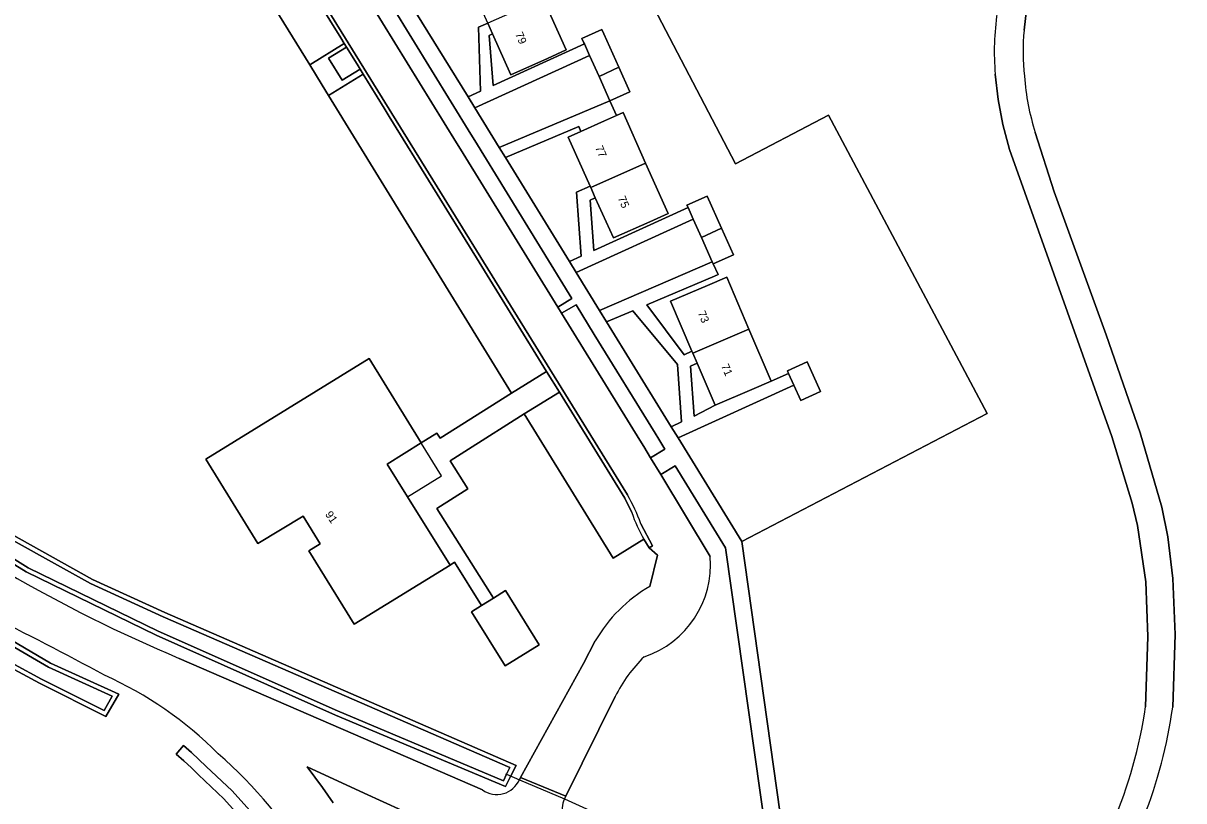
# Model space of a CAD drawing. Extents: x 158132 to 159664, y 385256 to 387218.
# Drawn here: x 158558.9 to 158703.8, y 386876.1 to 386973.2 of the extents above; entities that cross this region are included whole.
import ezdxf

# ---------------------------------------------------------------- set-up
doc = ezdxf.new("R2010")
doc.units = 0
for name, color, linetype in [('IMGEO_Duiker', 7, 'Continuous'), ('IMGEO_Erf', 7, 'Continuous'), ('IMGEO_Gemengd_bos', 7, 'Continuous'), ('IMGEO_Groenvoorziening', 7, 'Continuous'), ('IMGEO_Loofbos', 7, 'Continuous'), ('IMGEO_Oever', 7, 'Continuous'), ('IMGEO_Pand', 7, 'Continuous'), ('IMGEO_Pand_nummerreeks', 7, 'Continuous'), ('IMGEO_Pand_overbouw', 7, 'Continuous'), ('IMGEO_Parkeervlak_open', 7, 'Continuous'), ('IMGEO_Rijbaan_lokaal_gesloten', 7, 'Continuous'), ('IMGEO_Rijbaan_lokaal_open', 7, 'Continuous'), ('IMGEO_Voetpad_gesloten', 7, 'Continuous'), ('IMGEO_Voetpad_open', 7, 'Continuous'), ('IMGEO_Waterloop', 7, 'Continuous')]:
    doc.layers.add(name, color=color, linetype=linetype)

msp = doc.modelspace()

# ---------------------------------------------------------------- linework, layer by layer
at = {"layer": 'IMGEO_Duiker'}
msp.add_lwpolyline([(158619.11, 386879.44), (158619.24, 386879.39), (158620.83, 386878.7), (158626.46, 386876.3), (158630.15, 386874.64), (158630.33, 386874.56)], dxfattribs=at)
at = {"layer": 'IMGEO_Erf'}
msp.add_lwpolyline([(158623.8, 386976.31), (158626.68, 386969.87), (158624.35, 386968.82), (158619.78, 386966.78), (158617.49, 386971.89), (158617.08, 386971.7), (158617.54, 386965.43), (158628.95, 386970.64), (158628.9, 386970.75), (158628.65, 386971.31), (158631.15, 386972.43), (158631.4, 386971.87), (158633.25, 386967.74), (158634.64, 386964.63), (158632.15, 386963.51), (158632.96, 386961.69), (158633.78, 386962.05), (158636.6, 386955.75), (158639.43, 386949.45), (158637.13, 386948.42), (158632.57, 386946.38), (158630.32, 386951.39), (158629.67, 386951.09), (158630.14, 386944.82), (158641.9, 386950.19), (158641.77, 386950.48), (158644.28, 386951.61), (158646.08, 386947.6), (158647.57, 386944.29), (158645.05, 386943.16), (158645.66, 386941.8), (158645.19, 386941.6), (158636.77, 386938.03), (158641.41, 386931.79), (158642.39, 386932.24), (158639.73, 386938.48), (158644.33, 386940.45), (158646.74, 386941.48), (158649.51, 386934.98), (158652.28, 386928.48), (158654.46, 386929.47), (158654.32, 386929.79), (158656.77, 386930.89), (158658.43, 386927.19), (158655.98, 386926.09), (158655.12, 386928.01), (158640.65, 386921.41), (158648.61, 386908.46), (158679.26, 386924.45), (158659.44, 386961.72), (158647.81, 386955.65), (158601.87, 387043.7)], dxfattribs=at)
for points in [[(158614.02, 386979.67), (158614.66, 386979.95), (158614.41, 386980.51), (158613.22, 386979.97), (158610.46, 386978.77), (158606.42, 386977.01), (158614.42, 386964.01), (158615.97, 386964.72), (158615.71, 386972.73), (158616.9, 386973.22)], [(158630.78, 386966.57), (158629.61, 386969.17), (158615.27, 386962.63), (158618.31, 386957.7), (158632.15, 386963.51)], [(158626.92, 386958.98), (158628.51, 386959.69), (158628.24, 386960.3), (158619.08, 386956.45), (158627.09, 386943.43), (158628.56, 386944.1), (158627.97, 386952.1), (158629.66, 386952.87)], [(158644.93, 386943.42), (158643.58, 386946.43), (158642.56, 386948.72), (158627.94, 386942.05), (158630.85, 386937.34)], [(158640.57, 386930.58), (158635.02, 386937.29), (158631.73, 386935.9), (158638.81, 386924.4), (158639.8, 386922.79), (158641.1, 386923.39)], [(158643.03, 386930.74), (158642.21, 386930.37), (158642.68, 386924.1), (158645.27, 386925.49)]]:
    msp.add_lwpolyline(points, close=True, dxfattribs=at)
at = {"layer": 'IMGEO_Gemengd_bos'}
for points in [[(158687.81, 387060.41), (158689.82, 387061.16), (158703.82, 387101.71), (158681.04, 387088.11), (158663.51, 387076.57), (158660.41, 387074.96), (158660.01, 387075.7), (158644.04, 387067.33), (158614.63, 387050.48), (158601.87, 387043.7), (158647.81, 386955.65), (158659.44, 386961.72), (158679.26, 386924.45), (158648.61, 386908.46), (158655.38, 386860.52), (158656.73, 386859.94), (158667.25, 386855.4)], [(158699.03, 386887.81), (158699.33, 386896.58), (158699.08, 386903.41), (158698.06, 386910.44), (158697.36, 386913.26), (158694.85, 386921.58), (158682.07, 386957.44), (158681.23, 386960.57), (158680.64, 386963.69), (158680.28, 386966.85)]]:
    msp.add_lwpolyline(points, dxfattribs=at)
for centre, radius, start, end in [((158712.41, 386969.68), 32.26, 171.3349, 185.03), ((158644.17, 386895.43), 55.39, 336.384, 352.0933)]:
    msp.add_arc(centre, radius, start, end, dxfattribs=at)
at = {"layer": 'IMGEO_Groenvoorziening'}
for points in [[(158597.01, 386964.2), (158596.22, 386965.49), (158594.65, 386968.03), (158575.72, 386998.68)], [(158637.14, 386902.85), (158638.07, 386906.76), (158637.04, 386907.66), (158636.39, 386908.74), (158632.55, 386906.39), (158621.45, 386924.4), (158614.47, 386919.99), (158612.17, 386918.54), (158614.39, 386915.04), (158610.51, 386912.59), (158617.6, 386901.39), (158619.1, 386902.32), (158623.29, 386895.56), (158619.04, 386892.92), (158614.85, 386899.68), (158616.09, 386900.45), (158612.74, 386905.87), (158612.17, 386905.52), (158600.21, 386898.12), (158594.54, 386907.31), (158595.94, 386908.17), (158593.81, 386911.62), (158588.18, 386908.2), (158581.66, 386918.75), (158602.06, 386931.34), (158608.58, 386920.77), (158610.54, 386921.98), (158610.94, 386921.35), (158612.85, 386922.56), (158619.87, 386927), (158597.01, 386964.2)], [(158646.58, 386907.68), (158640.3, 386917.93), (158638.49, 386916.84), (158644.67, 386906.58)], [(158553.38, 386911.58), (158567.53, 386903.71), (158576.57, 386899.58), (158620.42, 386880.49), (158619.77, 386879.16), (158619.11, 386877.83), (158597.88, 386886.78), (158575.48, 386896.74), (158559.21, 386904.65), (158552.04, 386909.09)], [(158627.88, 386872.37), (158630.22, 386871.36), (158653.1, 386861.53), (158646.58, 386907.68)], [(158551.76, 386899.4), (158562.26, 386893.26), (158570.79, 386889.39), (158569.19, 386886.59), (158560.89, 386890.75), (158554.07, 386894.41), (158548.96, 386897.43), (158548.84, 386897.27)], [(158620.83, 386878.7), (158620.99, 386878.98), (158628.83, 386893.2), (158630.3, 386896.03)], [(158578.35, 386893.85), (158616.23, 386877.41)], [(158632.8, 386889.08), (158626.63, 386876.64), (158626.46, 386876.3)], [(158586.81, 386873.1), (158583.92, 386876.32), (158580.76, 386879.3), (158579.86, 386880.18), (158578.93, 386881.04), (158577.98, 386881.87), (158578.89, 386882.96), (158579.86, 386882.11), (158580.81, 386881.24), (158581.73, 386880.34), (158584.95, 386877.29), (158587.91, 386874)], [(158608.58, 386873.75), (158601.45, 386877.03), (158594.32, 386880.32), (158596.25, 386877.72), (158597.59, 386875.82)]]:
    msp.add_lwpolyline(points, dxfattribs=at)
for points in [[(158615.26, 386958.58), (158614.78, 386959.36), (158602.48, 386979.4), (158600.65, 386978.31), (158613, 386958.27), (158613.49, 386957.48), (158625.65, 386937.74), (158627.4, 386938.84)], [(158597.01, 386968.83), (158599.26, 386970.21), (158598.96, 386970.68), (158594.65, 386968.03), (158596.22, 386965.49), (158597.01, 386964.2), (158601.32, 386966.86), (158600.95, 386967.46), (158598.71, 386966.08)], [(158630.17, 386934.34), (158627.91, 386938.04), (158626.11, 386936.99), (158635.9, 386921.1), (158636.39, 386920.31), (158637.23, 386918.93), (158639.02, 386920.01), (158638.26, 386921.25), (158637.79, 386922)]]:
    msp.add_lwpolyline(points, close=True, dxfattribs=at)
for centre, radius, start, end in [((158654.05, 387072.79), 194.29, 232.8648, 247.0704), ((158632.57, 386905.57), 12.14, 288.5275, 4.7665), ((158646.8, 386886.32), 19.15, 120.2949, 149.5374), ((158290.06, 386372.24), 589.68, 61.7656, 63.37979), ((158649.18, 386880.95), 18.29, 134.2193, 153.6111), ((158549.31, 386848.03), 47.96, 44.9925, 65.7313), ((158546.29, 386839.62), 56.17, 30.2156, 48.8784), ((158618.02, 386879.89), 3.05, 234.0752, 337.0449), ((158629.12, 386875.04), 2.95, 154.6443, 244.9163)]:
    msp.add_arc(centre, radius, start, end, dxfattribs=at)
at = {"layer": 'IMGEO_Loofbos'}
for points in [[(158689.18, 387040.81), (158688.98, 387031.79), (158688.53, 387022.79), (158687.8, 387013.04), (158687.03, 387000), (158683.87, 386972.34)], [(158685.27, 386959.55), (158687.65, 386952.16), (158694.14, 386934.29), (158698.39, 386922.02), (158701.07, 386912.75), (158701.83, 386909.05), (158702.46, 386903.82), (158702.75, 386896.85), (158702.44, 386887.74)]]:
    msp.add_lwpolyline(points, dxfattribs=at)
for centre, radius, start, end in [((158711.54, 386969.64), 27.8, 174.423, 186.3133), ((158714.53, 386968.85), 30.7, 184.24, 197.6428), ((158642.89, 386896.04), 60.12, 338.462, 352.064)]:
    msp.add_arc(centre, radius, start, end, dxfattribs=at)
at = {"layer": 'IMGEO_Oever'}
for points in [[(158494.74, 386966.11), (158500, 386960.09), (158507.66, 386951.32), (158519.42, 386938.44), (158529.8, 386928.99), (158540.96, 386919.52), (158553.08, 386911.1), (158567.28, 386903.2), (158576.34, 386899.06), (158619.65, 386880.21), (158619.24, 386879.39), (158618.84, 386878.57), (158598.11, 386887.3)], [(158598.11, 386887.3), (158575.73, 386897.26), (158559.49, 386905.15), (158552.35, 386909.57), (158541.53, 386916.98), (158528.53, 386927.48), (158518.11, 386937.09), (158506.24, 386950.07), (158500, 386957.28), (158493.14, 386965.19)], [(158552.04, 386909.09), (158559.21, 386904.65), (158575.48, 386896.74), (158597.88, 386886.78), (158619.11, 386877.83), (158619.77, 386879.16), (158620.42, 386880.49), (158576.57, 386899.58), (158567.53, 386903.71), (158553.38, 386911.58)], [(158561.16, 386891.26), (158554.35, 386894.91), (158549.31, 386897.89), (158548.96, 386897.43), (158554.07, 386894.41), (158560.89, 386890.75), (158569.19, 386886.59), (158570.79, 386889.39), (158562.26, 386893.26), (158551.76, 386899.4)], [(158551.05, 386899.15), (158562, 386892.75), (158569.98, 386889.13), (158568.96, 386887.34), (158561.16, 386891.26)]]:
    msp.add_lwpolyline(points, dxfattribs=at)
at = {"layer": 'IMGEO_Pand'}
for points in [[(158623.8, 386976.31), (158616.9, 386973.22), (158617.49, 386971.89), (158619.78, 386966.78), (158624.35, 386968.82), (158626.68, 386969.87)], [(158631.4, 386971.87), (158631.15, 386972.43), (158628.65, 386971.31), (158628.9, 386970.75), (158628.95, 386970.64), (158629.61, 386969.17), (158630.78, 386966.57), (158633.25, 386967.74)], [(158633.25, 386967.74), (158630.78, 386966.57), (158632.15, 386963.51), (158634.64, 386964.63)], [(158633.78, 386962.05), (158632.96, 386961.69), (158631.48, 386961.02), (158628.51, 386959.69), (158626.92, 386958.98), (158629.66, 386952.87), (158629.74, 386952.68), (158636.6, 386955.75)], [(158636.6, 386955.75), (158629.74, 386952.68), (158630.32, 386951.39), (158632.57, 386946.38), (158637.13, 386948.42), (158639.43, 386949.45)], [(158644.28, 386951.61), (158641.77, 386950.48), (158641.9, 386950.19), (158642.56, 386948.72), (158643.58, 386946.43), (158646.08, 386947.6)], [(158646.08, 386947.6), (158643.58, 386946.43), (158644.93, 386943.42), (158645.05, 386943.16), (158647.57, 386944.29)], [(158646.74, 386941.48), (158644.33, 386940.45), (158639.73, 386938.48), (158642.39, 386932.24), (158642.5, 386931.99), (158649.51, 386934.98)], [(158649.51, 386934.98), (158642.5, 386931.99), (158643.03, 386930.74), (158645.27, 386925.49), (158649.87, 386927.45), (158652.28, 386928.48)], [(158604.31, 386918.14), (158608.58, 386920.77), (158602.06, 386931.34), (158581.66, 386918.75), (158588.18, 386908.2), (158593.81, 386911.62), (158595.94, 386908.17), (158594.54, 386907.31), (158600.21, 386898.12), (158612.17, 386905.52), (158606.86, 386914.04)], [(158656.77, 386930.89), (158654.32, 386929.79), (158654.46, 386929.47), (158655.12, 386928.01), (158655.98, 386926.09), (158658.43, 386927.19)], [(158619.1, 386902.32), (158617.6, 386901.39), (158616.09, 386900.45), (158614.85, 386899.68), (158619.04, 386892.92), (158623.29, 386895.56)]]:
    msp.add_lwpolyline(points, close=True, dxfattribs=at)
at = {"layer": 'IMGEO_Pand_overbouw'}
msp.add_lwpolyline([(158608.62, 386920.71), (158608.58, 386920.77), (158604.31, 386918.14), (158606.86, 386914.04), (158611.12, 386916.66)], close=True, dxfattribs=at)
at = {"layer": 'IMGEO_Parkeervlak_open'}
for points in [[(158579.93, 387001.32), (158575.72, 386998.68), (158594.65, 386968.03), (158598.96, 386970.68), (158598.52, 386971.41)], [(158601.32, 386966.86), (158597.01, 386964.2), (158619.87, 386927), (158624.24, 386929.68), (158615.46, 386943.91), (158604.58, 386961.57), (158603.95, 386962.59)]]:
    msp.add_lwpolyline(points, close=True, dxfattribs=at)
msp.add_lwpolyline([(158634.88, 386912.07), (158633.99, 386913.88), (158625.84, 386927.1), (158621.45, 386924.4), (158632.55, 386906.39), (158636.39, 386908.74)], dxfattribs=at)
msp.add_arc((158654.01, 386918.74), 20.27, 199.2354, 209.5693, dxfattribs=at)
at = {"layer": 'IMGEO_Rijbaan_lokaal_gesloten'}
for points in [[(158616.23, 386877.41), (158578.35, 386893.85)], [(158597.59, 386875.82), (158596.25, 386877.72), (158594.32, 386880.32), (158601.45, 386877.03), (158608.58, 386873.75)], [(158626.46, 386876.3), (158626.63, 386876.64), (158620.99, 386878.98), (158620.83, 386878.7)]]:
    msp.add_lwpolyline(points, dxfattribs=at)
for centre, radius, start, end in [((158654.05, 387072.79), 194.29, 232.8648, 247.0704), ((158290.06, 386372.24), 589.68, 61.7656, 63.37979), ((158549.31, 386848.03), 47.96, 44.9925, 65.7313), ((158546.29, 386839.62), 56.17, 30.2156, 48.8784), ((158618.02, 386879.89), 3.05, 234.0752, 337.0449), ((158629.12, 386875.04), 2.95, 154.6443, 244.9163)]:
    msp.add_arc(centre, radius, start, end, dxfattribs=at)
at = {"layer": 'IMGEO_Rijbaan_lokaal_open'}
for points in [[(158577.5, 387015.89), (158576.89, 387016.9), (158571.43, 387025.78), (158569.56, 387024.62), (158568.02, 387023.67), (158567.57, 387023.39), (158567.71, 387023.13), (158556.62, 387015.67), (158561.68, 387007.69), (158564.89, 387006.54), (158568.36, 387005.47), (158571.86, 387004.58), (158574.81, 387004.23), (158577.39, 387004.29), (158578.52, 387004.51), (158580.35, 387001.58), (158581.34, 387000), (158585.64, 386993.16), (158585.72, 386993.03), (158634.35, 386914.28)], [(158644.67, 386906.58), (158638.49, 386916.84), (158637.23, 386918.93), (158636.39, 386920.31), (158635.9, 386921.1), (158626.11, 386936.99), (158625.65, 386937.74), (158613.49, 386957.48), (158613, 386958.27), (158600.65, 386978.31), (158600.17, 386979.09), (158587.81, 386999.16), (158587.29, 387000), (158586.83, 387000.75), (158577.5, 387015.89)], [(158585.72, 386993.03), (158585.64, 386993.16), (158581.34, 387000), (158580.35, 387001.58), (158579.93, 387001.32), (158598.52, 386971.41), (158598.96, 386970.68), (158599.26, 386970.21), (158600.56, 386968.1), (158600.95, 386967.46), (158601.32, 386966.86), (158603.95, 386962.59), (158604.58, 386961.57), (158615.46, 386943.91), (158624.24, 386929.68), (158625.84, 386927.1), (158633.99, 386913.88), (158634.88, 386912.07)], [(158634.35, 386914.28), (158585.72, 386993.03)], [(158636.39, 386908.74), (158637.04, 386907.66), (158637.46, 386907.91), (158636, 386910.68)], [(158636, 386910.68), (158637.46, 386907.91), (158637.04, 386907.66), (158638.07, 386906.76), (158637.14, 386902.85)], [(158630.3, 386896.03), (158628.83, 386893.2), (158620.99, 386878.98), (158626.63, 386876.64), (158632.8, 386889.08)]]:
    msp.add_lwpolyline(points, dxfattribs=at)
for centre, radius, start, end in [((158612.98, 386902.31), 24.49, 19.9902, 29.2734), ((158612.98, 386902.31), 24.49, 19.9902, 29.2734), ((158654.01, 386918.74), 20.27, 199.2354, 209.5693), ((158632.57, 386905.57), 12.14, 288.5275, 4.7665), ((158646.8, 386886.32), 19.15, 120.2949, 149.5374), ((158649.18, 386880.95), 18.29, 134.2193, 153.6111)]:
    msp.add_arc(centre, radius, start, end, dxfattribs=at)
at = {"layer": 'IMGEO_Voetpad_gesloten'}
for points in [[(158602.48, 386979.4), (158614.78, 386959.36), (158615.26, 386958.58), (158627.4, 386938.84), (158625.65, 386937.74), (158626.11, 386936.99), (158627.91, 386938.04), (158630.17, 386934.34), (158637.79, 386922), (158638.26, 386921.25), (158639.02, 386920.01), (158637.23, 386918.93), (158638.49, 386916.84), (158640.3, 386917.93), (158646.58, 386907.68), (158653.1, 386861.53)], [(158655.38, 386860.52), (158648.61, 386908.46), (158640.65, 386921.41), (158639.8, 386922.79), (158638.81, 386924.4), (158631.73, 386935.9), (158630.85, 386937.34), (158627.94, 386942.05), (158627.09, 386943.43), (158619.08, 386956.45), (158618.31, 386957.7), (158615.27, 386962.63), (158614.42, 386964.01), (158606.42, 386977.01)]]:
    msp.add_lwpolyline(points, dxfattribs=at)
at = {"layer": 'IMGEO_Voetpad_open'}
for points in [[(158683.87, 386972.34), (158687.03, 387000), (158687.8, 387013.04), (158688.53, 387022.79), (158688.98, 387031.79), (158689.18, 387040.81), (158689.13, 387040.98), (158690.52, 387056.33)], [(158680.28, 386966.85), (158680.64, 386963.69), (158681.23, 386960.57), (158682.07, 386957.44), (158694.85, 386921.58), (158697.36, 386913.26), (158698.06, 386910.44), (158699.08, 386903.41), (158699.33, 386896.58), (158699.03, 386887.81)], [(158702.44, 386887.74), (158702.75, 386896.85), (158702.46, 386903.82), (158701.83, 386909.05), (158701.07, 386912.75), (158698.39, 386922.02), (158694.14, 386934.29), (158687.65, 386952.16), (158685.27, 386959.55)]]:
    msp.add_lwpolyline(points, dxfattribs=at)
for points in [[(158629.61, 386969.17), (158628.95, 386970.64), (158617.54, 386965.43), (158617.08, 386971.7), (158617.49, 386971.89), (158616.9, 386973.22), (158615.71, 386972.73), (158615.97, 386964.72), (158614.42, 386964.01), (158615.27, 386962.63)], [(158600.56, 386968.1), (158599.26, 386970.21), (158597.01, 386968.83), (158598.71, 386966.08), (158600.95, 386967.46)], [(158632.96, 386961.69), (158632.15, 386963.51), (158618.31, 386957.7), (158619.08, 386956.45), (158628.24, 386960.3), (158628.51, 386959.69), (158631.48, 386961.02)], [(158642.56, 386948.72), (158641.9, 386950.19), (158630.14, 386944.82), (158629.67, 386951.09), (158630.32, 386951.39), (158629.74, 386952.68), (158629.66, 386952.87), (158627.97, 386952.1), (158628.56, 386944.1), (158627.09, 386943.43), (158627.94, 386942.05)], [(158655.12, 386928.01), (158654.46, 386929.47), (158652.28, 386928.48), (158649.87, 386927.45), (158645.27, 386925.49), (158642.68, 386924.1), (158642.21, 386930.37), (158643.03, 386930.74), (158642.5, 386931.99), (158642.39, 386932.24), (158641.41, 386931.79), (158636.77, 386938.03), (158645.19, 386941.6), (158645.66, 386941.8), (158645.05, 386943.16), (158644.93, 386943.42), (158630.85, 386937.34), (158631.73, 386935.9), (158635.02, 386937.29), (158640.57, 386930.58), (158641.1, 386923.39), (158639.8, 386922.79), (158640.65, 386921.41)], [(158621.45, 386924.4), (158625.84, 386927.1), (158624.24, 386929.68), (158619.87, 386927), (158612.85, 386922.56), (158610.94, 386921.35), (158610.54, 386921.98), (158608.58, 386920.77), (158604.31, 386918.14), (158606.86, 386914.04), (158612.17, 386905.52), (158612.74, 386905.87), (158616.09, 386900.45), (158617.6, 386901.39), (158610.51, 386912.59), (158614.39, 386915.04), (158612.17, 386918.54), (158614.47, 386919.99)]]:
    msp.add_lwpolyline(points, close=True, dxfattribs=at)
for centre, radius, start, end in [((158712.41, 386969.68), 32.26, 171.3349, 185.03), ((158711.54, 386969.64), 27.8, 174.423, 186.3133), ((158714.53, 386968.85), 30.7, 184.24, 197.6428), ((158644.17, 386895.43), 55.39, 336.384, 352.0933), ((158642.89, 386896.04), 60.12, 338.462, 352.064)]:
    msp.add_arc(centre, radius, start, end, dxfattribs=at)
at = {"layer": 'IMGEO_Waterloop'}
for points in [[(158493.14, 386965.19), (158500, 386957.28), (158506.24, 386950.07), (158518.11, 386937.09), (158528.53, 386927.48), (158541.53, 386916.98), (158552.35, 386909.57), (158559.49, 386905.15), (158575.73, 386897.26), (158598.11, 386887.3), (158618.84, 386878.57), (158619.24, 386879.39), (158619.65, 386880.21), (158576.34, 386899.06), (158567.28, 386903.2), (158553.08, 386911.1), (158540.96, 386919.52), (158529.8, 386928.99), (158519.42, 386938.44), (158507.66, 386951.32), (158500, 386960.09), (158494.74, 386966.11)], [(158562, 386892.75), (158551.05, 386899.15)], [(158549.31, 386897.89), (158554.35, 386894.91), (158561.16, 386891.26), (158568.96, 386887.34), (158569.98, 386889.13), (158562, 386892.75)], [(158587.91, 386874), (158584.95, 386877.29), (158581.73, 386880.34), (158580.81, 386881.24), (158579.86, 386882.11), (158578.89, 386882.96), (158577.98, 386881.87), (158578.93, 386881.04), (158579.86, 386880.18), (158580.76, 386879.3), (158583.92, 386876.32), (158586.81, 386873.1)]]:
    msp.add_lwpolyline(points, dxfattribs=at)

# ---------------------------------------------------------------- texts
at = {"layer": 'IMGEO_Pand_nummerreeks'}
for s, rotation, p in [('79', 292.9754, (158620.29, 386971.86)), ('77', 292.9754, (158630.28, 386957.68)), ('75', 292.9754, (158633.11, 386951.37)), ('73', 292.9754, (158643.09, 386937.03)), ('71', 292.9754, (158646.01, 386930.4)), ('91', 303.9475, (158596.53, 386911.85))]:
    msp.add_text(s, height=1, rotation=rotation, dxfattribs=at).set_placement(p)

doc.saveas('drawing.dxf')
